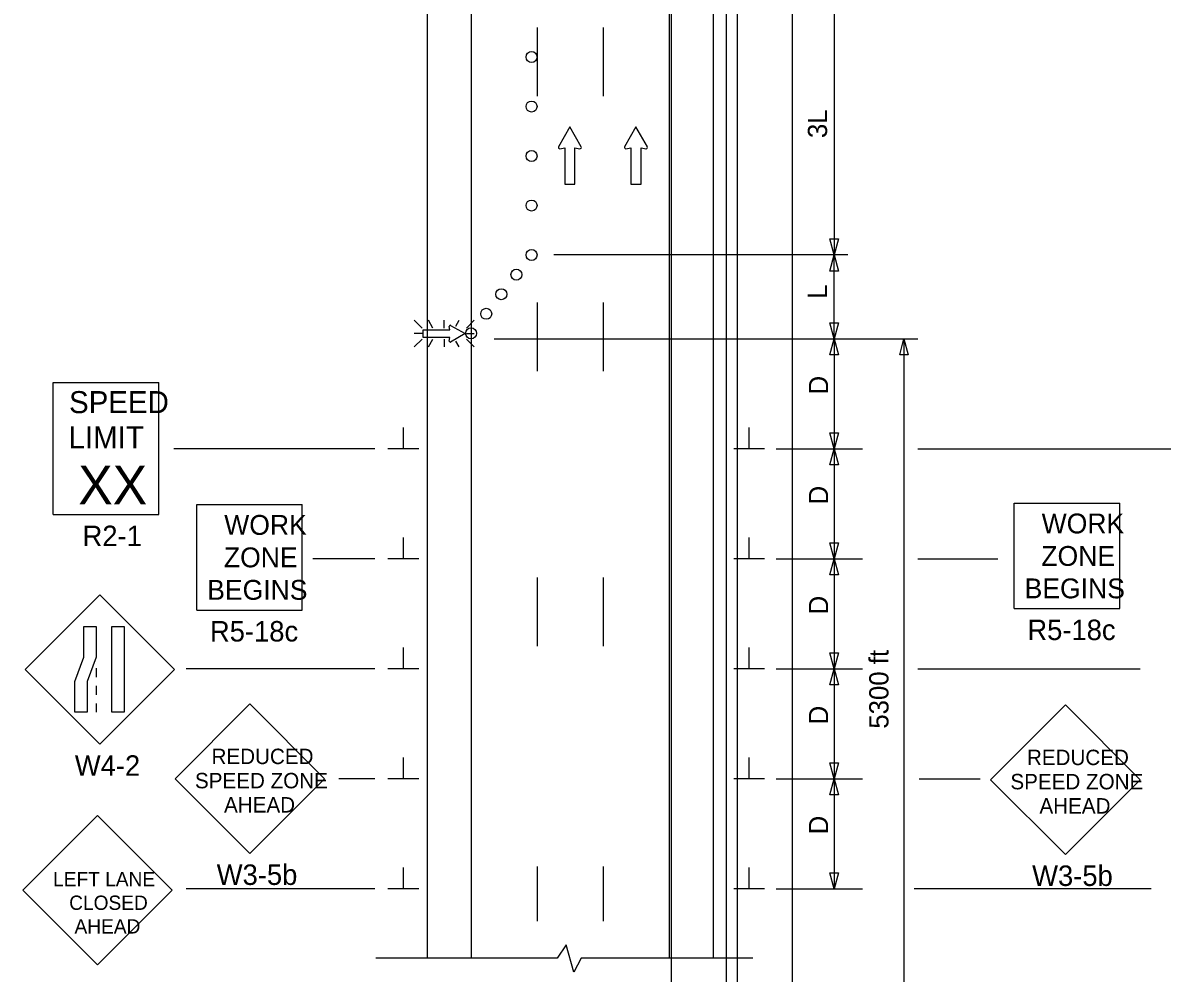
# Model space of a CAD drawing. Extents: x 16590 to 19504, y 5703 to 6974.
# Drawn here: x 16744.8 to 17159.2, y 6276.8 to 6622.4 of the extents above; entities that cross this region are included whole.
import ezdxf

# ---------------------------------------------------------------- set-up
doc = ezdxf.new("R2010")
doc.units = 0
for name, color, linetype in [('ALI_LEGAL_EX', 7, 'Continuous'), ('MT_SCRATCH_LEVEL_E', 7, 'Continuous'), ('PAVT_EDGE_EX', 7, 'Continuous'), ('TRAFFIC_SIGNS_PR', 7, 'Continuous'), ('TYPICAL_TEXT_DIMEN_PR', 7, 'Continuous')]:
    doc.layers.add(name, color=color, linetype=linetype)

msp = doc.modelspace()

# ---------------------------------------------------------------- linework, layer by layer
at = {"layer": 'ALI_LEGAL_EX'}
for p, q in [((16980.68, 6974.12), (16980.68, 6155.98)), ((17004.68, 6974.12), (17004.68, 6155.98)), ((17000.61, 6922.21), (17000.61, 6058.3)), ((17024.61, 6922.21), (17024.61, 6058.3))]:
    msp.add_line(p, q, dxfattribs=at)
for points in [[(16931.89, 6620.69), (16931.89, 6595.69)], [(16955.89, 6620.69), (16955.89, 6595.69)], [(16931.89, 6520.69), (16931.89, 6495.69)], [(16955.89, 6520.69), (16955.89, 6495.69)], [(16931.89, 6420.69), (16931.89, 6395.69)], [(16955.89, 6420.69), (16955.89, 6395.69)], [(16931.89, 6315.64), (16931.89, 6295.69)], [(16955.89, 6315.64), (16955.89, 6295.69)]]:
    msp.add_lwpolyline(points, dxfattribs=at)
at = {"layer": 'MT_SCRATCH_LEVEL_E'}
for p, q in [((16943.79, 6584.55), (16939.68, 6577.31)), ((16947.94, 6577.31), (16943.79, 6584.55)), ((16967.84, 6584.55), (16963.73, 6577.31)), ((16971.99, 6577.31), (16967.84, 6584.55)), ((16940.16, 6576.63), (16941.94, 6576.94)), ((16941.94, 6576.94), (16941.94, 6563.69)), ((16945.68, 6563.69), (16945.68, 6576.94)), ((16945.68, 6576.94), (16947.46, 6576.63)), ((16964.22, 6576.63), (16965.99, 6576.94)), ((16965.99, 6576.94), (16965.99, 6563.69)), ((16969.73, 6563.69), (16969.73, 6576.94)), ((16969.73, 6576.94), (16971.51, 6576.63)), ((16941.94, 6563.69), (16945.68, 6563.69)), ((16965.99, 6563.69), (16969.73, 6563.69))]:
    msp.add_line(p, q, dxfattribs=at)
for centre, start, end in [((16940.09, 6577.09), 150.4248, 279.9638), ((16947.53, 6577.09), 260.0362, 29.7731), ((16964.14, 6577.09), 150.4248, 279.9638), ((16971.58, 6577.09), 260.0362, 29.7731)]:
    msp.add_arc(centre, 0.463, start, end, dxfattribs=at)
at = {"layer": 'PAVT_EDGE_EX'}
for p, q in [((16891.89, 6927.73), (16891.89, 6507.47)), ((16907.89, 6927.73), (16907.89, 6507.47)), ((16979.89, 6927.73), (16979.89, 6507.47)), ((16995.89, 6927.73), (16995.89, 6507.47)), ((16891.89, 6507.47), (16891.89, 6282.26)), ((16907.89, 6507.47), (16907.89, 6282.26)), ((16979.89, 6507.47), (16979.89, 6282.26)), ((16995.89, 6507.47), (16995.89, 6282.26))]:
    msp.add_line(p, q, dxfattribs=at)
at = {"layer": 'TRAFFIC_SIGNS_PR'}
for p, q in [((16890.05, 6511.4), (16887.23, 6514.22)), ((16894, 6511.4), (16892.37, 6514.22)), ((16898.14, 6511.4), (16898.14, 6514.22)), ((16902.32, 6512.04), (16903.58, 6514.22)), ((16909.04, 6514.22), (16906.22, 6511.4)), ((16890.05, 6509.37), (16887.23, 6509.37)), ((16890.05, 6507.34), (16887.23, 6504.52)), ((16892.35, 6504.52), (16893.98, 6507.34)), ((16898.14, 6507.34), (16898.14, 6504.52)), ((16903.6, 6504.52), (16902.4, 6506.61)), ((16906.22, 6509.37), (16909.04, 6509.37)), ((16909.04, 6504.52), (16906.22, 6507.34)), ((16755.9, 6491.61), (16794.34, 6491.61)), ((16755.9, 6443.55), (16755.9, 6491.61)), ((16794.34, 6443.55), (16794.34, 6491.61)), ((16808.11, 6408.85), (16808.11, 6447.25)), ((16808.11, 6447.25), (16846.51, 6447.25)), ((16846.51, 6408.85), (16846.51, 6447.25)), ((17105.4, 6409.37), (17105.4, 6447.77)), ((17105.4, 6447.77), (17143.8, 6447.77)), ((17143.8, 6409.37), (17143.8, 6447.77)), ((16755.9, 6443.55), (16794.34, 6443.55)), ((16772.82, 6414.33), (16745.67, 6387.18)), ((16799.97, 6387.18), (16772.82, 6414.33)), ((16808.11, 6408.85), (16846.51, 6408.85)), ((17105.4, 6409.37), (17143.8, 6409.37)), ((16745.67, 6387.18), (16772.82, 6360.03)), ((16771.57, 6387.67), (16771.57, 6384.47)), ((16772.82, 6360.03), (16799.97, 6387.18)), ((16771.57, 6381.27), (16771.57, 6378.07)), ((16771.57, 6374.87), (16771.57, 6371.67)), ((16827.45, 6374.71), (16800.26, 6347.52)), ((16854.63, 6347.52), (16827.45, 6374.71)), ((17124.01, 6374.34), (17096.82, 6347.15)), ((17151.19, 6347.15), (17124.01, 6374.34)), ((16800.26, 6347.52), (16827.45, 6320.33)), ((16827.45, 6320.33), (16854.63, 6347.52)), ((17096.82, 6347.15), (17124.01, 6319.96)), ((17124.01, 6319.96), (17151.19, 6347.15)), ((16772, 6334.17), (16744.85, 6307.02)), ((16799.15, 6307.02), (16772, 6334.17)), ((16744.85, 6307.02), (16772, 6279.86)), ((16772, 6279.86), (16799.15, 6307.02))]:
    msp.add_line(p, q, dxfattribs=at)
for points in [[(16899.96, 6506.69), (16900.19, 6507.99), (16890.47, 6507.99), (16890.47, 6510.73), (16900.19, 6510.73), (16899.96, 6512.03)], [(16900.46, 6512.39), (16905.77, 6509.37), (16900.46, 6506.33)]]:
    msp.add_lwpolyline(points, dxfattribs=at)
for points in [[(16771.57, 6402.92), (16771.57, 6391.74), (16768.23, 6382.85), (16768.23, 6371.67), (16763.73, 6371.67), (16763.73, 6382.85), (16767.08, 6391.74), (16767.08, 6402.92)], [(16781.71, 6402.92), (16781.71, 6371.67), (16777.21, 6371.67), (16777.21, 6402.92)]]:
    msp.add_lwpolyline(points, close=True, dxfattribs=at)
for centre in [(16929.88, 6609.98), (16929.88, 6591.98), (16929.88, 6573.98), (16929.88, 6555.98), (16929.88, 6537.98), (16929.88, 6537.98), (16929.88, 6537.98), (16929.88, 6537.98), (16924.38, 6530.85), (16918.88, 6523.72), (16913.39, 6516.59), (16907.89, 6509.47)]:
    msp.add_circle(centre, 2, dxfattribs=at)
for centre, start, end in [((16900.3, 6512.09), 61.1084, 189.2692), ((16900.3, 6506.63), 170.0407, 298.5167)]:
    msp.add_arc(centre, 0.341, start, end, dxfattribs=at)
at = {"layer": 'TYPICAL_TEXT_DIMEN_PR'}
for p, q in [((17039.98, 6630.03), (17039.89, 6537.98)), ((17039.89, 6537.98), (17038.32, 6543.84)), ((17038.32, 6543.84), (17039.89, 6543.84)), ((17039.89, 6543.84), (17041.46, 6543.84)), ((17041.46, 6543.84), (17039.89, 6537.98)), ((17044.89, 6537.98), (16937.97, 6537.98)), ((17038.32, 6532.12), (17039.89, 6537.98)), ((17039.89, 6507.47), (17039.89, 6537.98)), ((17039.89, 6537.98), (17041.46, 6532.12)), ((17039.89, 6532.12), (17038.32, 6532.12)), ((17041.46, 6532.12), (17039.89, 6532.12)), ((17039.89, 6507.47), (17038.32, 6513.33)), ((17038.32, 6513.33), (17039.89, 6513.33)), ((17039.89, 6513.33), (17041.46, 6513.33)), ((17041.46, 6513.33), (17039.89, 6507.47)), ((16916.29, 6507.47), (17070.33, 6507.47)), ((17038.32, 6501.61), (17039.89, 6507.47)), ((17039.89, 6507.47), (17039.89, 6467.47)), ((17039.89, 6507.47), (17041.46, 6501.61)), ((17063.76, 6501.61), (17065.33, 6507.47)), ((17065.33, 6507.47), (17065.33, 6231.79)), ((17065.33, 6507.47), (17066.9, 6501.61)), ((17039.89, 6501.61), (17038.32, 6501.61)), ((17041.46, 6501.61), (17039.89, 6501.61)), ((17065.33, 6501.61), (17063.76, 6501.61)), ((17066.9, 6501.61), (17065.33, 6501.61)), ((16883.26, 6467.46), (16883.26, 6475.24)), ((17009.01, 6467.46), (17009.01, 6475.24)), ((17039.89, 6467.47), (17038.32, 6473.33)), ((17038.32, 6473.33), (17039.89, 6473.33)), ((17039.89, 6473.33), (17041.46, 6473.33)), ((17041.46, 6473.33), (17039.89, 6467.47)), ((16872.84, 6467.47), (16799.73, 6467.47)), ((16888.89, 6467.46), (16877.64, 6467.46)), ((17014.64, 6467.46), (17003.39, 6467.46)), ((17018.89, 6467.47), (17050.2, 6467.47)), ((17038.32, 6461.61), (17039.89, 6467.47)), ((17039.89, 6467.47), (17039.89, 6427.47)), ((17039.89, 6467.47), (17041.46, 6461.61)), ((17070.33, 6467.47), (17165.43, 6467.47)), ((17039.89, 6461.61), (17038.32, 6461.61)), ((17041.46, 6461.61), (17039.89, 6461.61)), ((16883.26, 6427.46), (16883.26, 6435.24)), ((17009.01, 6427.46), (17009.01, 6435.24)), ((17039.89, 6427.47), (17038.32, 6433.33)), ((17038.32, 6433.33), (17039.89, 6433.33)), ((17039.89, 6433.33), (17041.46, 6433.33)), ((17041.46, 6433.33), (17039.89, 6427.47)), ((16872.84, 6427.47), (16850.31, 6427.47)), ((16888.89, 6427.46), (16877.64, 6427.46)), ((17014.64, 6427.46), (17003.39, 6427.46)), ((17018.89, 6427.47), (17050.2, 6427.47)), ((17038.32, 6421.61), (17039.89, 6427.47)), ((17039.89, 6427.47), (17039.89, 6387.47)), ((17039.89, 6427.47), (17041.46, 6421.61)), ((17070.33, 6427.47), (17099.49, 6427.47)), ((17039.89, 6421.61), (17038.32, 6421.61)), ((17041.46, 6421.61), (17039.89, 6421.61)), ((16883.26, 6387.46), (16883.26, 6395.24)), ((17009.01, 6387.46), (17009.01, 6395.24)), ((17039.89, 6387.47), (17038.32, 6393.33)), ((17038.32, 6393.33), (17039.89, 6393.33)), ((17039.89, 6393.33), (17041.46, 6393.33)), ((17041.46, 6393.33), (17039.89, 6387.47)), ((16872.84, 6387.47), (16804.24, 6387.47)), ((16888.89, 6387.46), (16877.64, 6387.46)), ((17014.64, 6387.46), (17003.39, 6387.46)), ((17018.89, 6387.47), (17050.2, 6387.47)), ((17038.32, 6381.61), (17039.89, 6387.47)), ((17039.89, 6387.47), (17039.89, 6347.47)), ((17039.89, 6387.47), (17041.46, 6381.61)), ((17070.33, 6387.47), (17151.18, 6387.47)), ((17039.89, 6381.61), (17038.32, 6381.61)), ((17041.46, 6381.61), (17039.89, 6381.61)), ((16883.26, 6347.46), (16883.26, 6355.24)), ((17009.01, 6347.46), (17009.01, 6355.24)), ((17039.89, 6347.47), (17038.32, 6353.33)), ((17038.32, 6353.33), (17039.89, 6353.33)), ((17039.89, 6353.33), (17041.46, 6353.33)), ((17041.46, 6353.33), (17039.89, 6347.47)), ((16872.84, 6347.47), (16859.74, 6347.47)), ((16888.89, 6347.46), (16877.64, 6347.46)), ((17014.64, 6347.46), (17003.39, 6347.46)), ((17018.89, 6347.47), (17050.2, 6347.47)), ((17038.32, 6341.61), (17039.89, 6347.47)), ((17039.89, 6347.47), (17039.89, 6307.47)), ((17039.89, 6347.47), (17041.46, 6341.61)), ((17070.87, 6347.47), (17093.03, 6347.47)), ((17039.89, 6341.61), (17038.32, 6341.61)), ((17041.46, 6341.61), (17039.89, 6341.61)), ((16883.26, 6307.46), (16883.26, 6315.24)), ((17009.01, 6307.46), (17009.01, 6315.24)), ((17039.89, 6307.47), (17038.32, 6313.33)), ((17038.32, 6313.33), (17039.89, 6313.33)), ((17039.89, 6313.33), (17041.46, 6313.33)), ((17041.46, 6313.33), (17039.89, 6307.47)), ((16872.84, 6307.47), (16804.24, 6307.47)), ((16888.89, 6307.46), (16877.64, 6307.46)), ((17014.64, 6307.46), (17003.39, 6307.46)), ((17018.89, 6307.47), (17050.2, 6307.47)), ((17155.22, 6307.47), (17069.07, 6307.47)), ((16942.49, 6287.06), (16939.24, 6282.26)), ((16945.23, 6277.12), (16942.49, 6287.06)), ((16939.24, 6282.26), (16873.3, 6282.26)), ((16947.98, 6282.26), (16945.23, 6277.12)), ((17010.31, 6282.26), (16947.98, 6282.26))]:
    msp.add_line(p, q, dxfattribs=at)

# ---------------------------------------------------------------- texts
at = {"layer": 'TRAFFIC_SIGNS_PR'}
for s, height, p in [('SPEED', 8.01, (16761.67, 6480.46)), ('LIMIT', 8.01, (16761.51, 6467.64)), ('XX', 14.048, (16765.02, 6447.31)), ('WORK', 7.217, (17115.4, 6436.73)), ('R2-1', 7.449, (16766.58, 6432.1)), ('WORK', 7.217, (16818.11, 6436.21)), ('ZONE', 7.217, (16817.99, 6424.4)), ('ZONE', 7.217, (17115.28, 6424.92)), ('BEGINS', 7.217, (16811.92, 6412.59)), ('BEGINS', 7.217, (17109.21, 6413.12)), ('R5-18c', 7.44, (16812.92, 6397.41)), ('R5-18c', 7.44, (17110.21, 6397.93)), ('REDUCED', 5.607, (16813.49, 6352.83)), ('REDUCED', 5.607, (17110.05, 6352.46)), ('W4-2', 7.44, (16763.78, 6348.59)), ('SPEED ZONE', 5.607, (16807.47, 6344.02)), ('SPEED ZONE', 5.607, (17104.03, 6343.65)), ('AHEAD', 5.607, (16818.04, 6335.21)), ('AHEAD', 5.607, (17114.6, 6334.84)), ('W3-5b', 7.449, (16815.38, 6308.88)), ('W3-5b', 7.449, (17111.94, 6308.51)), ('LEFT LANE', 5.2, (16755.88, 6308.41)), ('CLOSED', 5.2, (16761.72, 6299.81)), ('AHEAD', 5.2, (16763.66, 6291.21))]:
    msp.add_text(s, height=height, dxfattribs=at).set_placement(p)
at = {"layer": 'TYPICAL_TEXT_DIMEN_PR'}
for s, p in [('3L', (17037.37, 6580.51)), ('L', (17037.33, 6522.08)), ('D', (17037.73, 6487.28)), ('D', (17037.73, 6447.28)), ('D', (17037.73, 6407.28)), ('5300 ft', (17059.69, 6365.71)), ('D', (17037.73, 6367.28)), ('D', (17037.73, 6327.28))]:
    msp.add_text(s, height=7, rotation=90, dxfattribs=at).set_placement(p)

doc.saveas('drawing.dxf')
